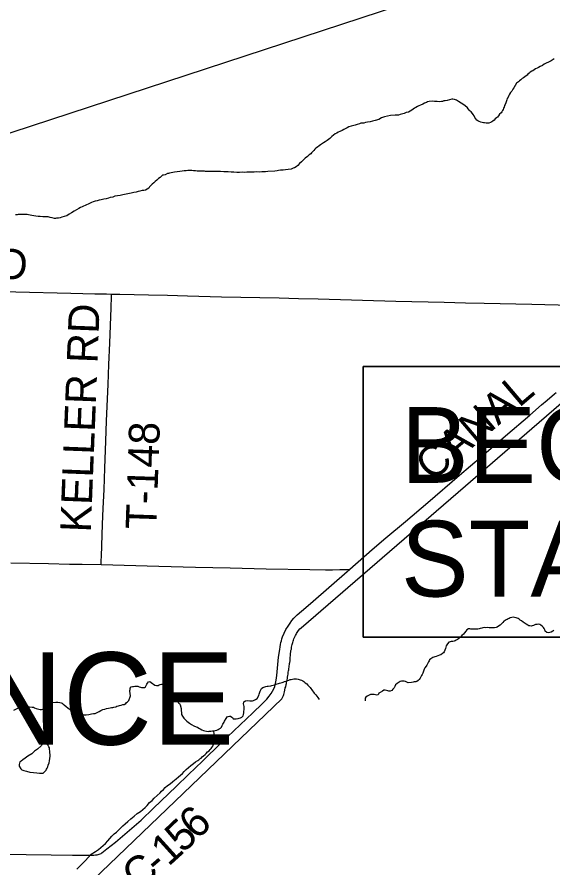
# Model space of a CAD drawing. Extents: x 0 to 34, y 0 to 22.
# Drawn here: x 24.635 to 25.625, y 15.894 to 17.466 of the extents above; entities that cross this region are included whole.
import ezdxf

# ---------------------------------------------------------------- set-up
doc = ezdxf.new("R2010")
doc.units = 0
for name, color, linetype in [('GM_X_County_Road', 7, 'Continuous'), ('GM_X_County_Road_Text', 7, 'Continuous'), ('GM_X_Minor_Lake', 7, 'Continuous'), ('GM_X_Minor_River', 7, 'Continuous'), ('GM_X_Rail_Line', 7, 'Continuous'), ('GM_X_Township_Road', 7, 'Continuous'), ('GM_X_Township_Road_Text', 7, 'Continuous'), ('GM_X_Township_Text', 7, 'Continuous'), ('SH_Masking', 7, 'Continuous'), ('SH_Text', 7, 'Continuous')]:
    doc.layers.add(name, color=color, linetype=linetype)

msp = doc.modelspace()

# ---------------------------------------------------------------- linework, layer by layer
at = {"layer": 'GM_X_County_Road'}
for points in [[(25.2499, 16.446), (25.2909, 16.4827), (25.3163, 16.5037), (25.3525, 16.5341), (25.3935, 16.5693), (25.4522, 16.6194), (25.4927, 16.6543), (25.5372, 16.6923), (25.582, 16.7308), (25.6039, 16.7493), (25.614, 16.7581), (25.6278, 16.7698), (25.6309, 16.7725)], [(24.6233, 16.4577), (24.6929, 16.4566), (24.7314, 16.4555), (24.755, 16.4552), (24.79, 16.4546)], [(24.79, 16.4546), (24.8967, 16.4517), (24.9645, 16.4499), (25.0285, 16.4483), (25.095, 16.4466), (25.1756, 16.4452), (25.2047, 16.445), (25.2176, 16.445), (25.2311, 16.4452), (25.2384, 16.4455), (25.2442, 16.4457), (25.2499, 16.446)], [(24.7913, 15.922), (24.8009, 15.9294), (24.8166, 15.9416), (24.8639, 15.9828), (24.8869, 16.0046), (24.9286, 16.0446), (24.9518, 16.0671), (24.9774, 16.0916), (25.0122, 16.1253), (25.0703, 16.1807), (25.0877, 16.1975), (25.096, 16.2058), (25.1008, 16.2114), (25.1046, 16.2165), (25.107, 16.2205), (25.1092, 16.2249), (25.1109, 16.2294), (25.1125, 16.2349), (25.1136, 16.241), (25.1145, 16.2494), (25.1179, 16.2834), (25.12, 16.2976), (25.1207, 16.3027), (25.1215, 16.3069), (25.1224, 16.3106), (25.1232, 16.3137), (25.1243, 16.3174), (25.1255, 16.3209), (25.1283, 16.3277), (25.1316, 16.3344), (25.1354, 16.3409), (25.1393, 16.3466), (25.1427, 16.3511), (25.1464, 16.3554), (25.1526, 16.3615), (25.1605, 16.3686), (25.1772, 16.3826), (25.2499, 16.446)]]:
    msp.add_lwpolyline(points, dxfattribs=at)
at = {"layer": 'GM_X_Minor_Lake'}
for points in [[(24.6836, 16.128), (24.6832, 16.1265), (24.6792, 16.1198), (24.6725, 16.1139), (24.667, 16.1099), (24.6619, 16.1048), (24.6549, 16.1008), (24.6499, 16.0972), (24.6456, 16.0939), (24.6421, 16.0917), (24.6401, 16.0903), (24.6384, 16.0854), (24.6387, 16.0823), (24.642, 16.0773), (24.6439, 16.0757), (24.6472, 16.0745), (24.6521, 16.0728), (24.6586, 16.0714), (24.6654, 16.0704), (24.6715, 16.0698), (24.6764, 16.0693)], [(24.6836, 16.128), (24.6832, 16.1265), (24.6792, 16.1198), (24.6725, 16.1139), (24.667, 16.1099), (24.6619, 16.1048), (24.6549, 16.1008), (24.6499, 16.0972), (24.6456, 16.0939), (24.6421, 16.0917), (24.6401, 16.0903), (24.6384, 16.0854), (24.6387, 16.0823), (24.642, 16.0773), (24.6439, 16.0757), (24.6472, 16.0745), (24.6521, 16.0728), (24.6586, 16.0714), (24.6654, 16.0704), (24.6715, 16.0698), (24.6764, 16.0693), (24.6806, 16.0695), (24.6829, 16.0695), (24.686, 16.0724), (24.6884, 16.0746), (24.6892, 16.0765), (24.6904, 16.0787), (24.6916, 16.081), (24.6925, 16.084), (24.6941, 16.0881), (24.695, 16.0919), (24.6955, 16.0961), (24.6957, 16.1006), (24.6958, 16.104), (24.6955, 16.1067), (24.6956, 16.1086), (24.6952, 16.1105), (24.6949, 16.1132), (24.6947, 16.1163), (24.6936, 16.1182), (24.6921, 16.1205), (24.6836, 16.128)], [(24.6764, 16.0693), (24.6806, 16.0695), (24.6829, 16.0695), (24.686, 16.0724), (24.6884, 16.0746), (24.6892, 16.0765), (24.6904, 16.0787), (24.6916, 16.081), (24.6925, 16.084), (24.6941, 16.0881), (24.695, 16.0919), (24.6955, 16.0961), (24.6957, 16.1006), (24.6958, 16.104), (24.6955, 16.1067), (24.6956, 16.1086), (24.6952, 16.1105), (24.6949, 16.1132), (24.6947, 16.1163), (24.6936, 16.1182), (24.6921, 16.1205), (24.6836, 16.128)]]:
    msp.add_lwpolyline(points, dxfattribs=at)
at = {"layer": 'GM_X_Minor_River'}
msp.add_line((23.5167, 14.667), (25.1242, 16.2064), dxfattribs=at)
for points in [[(25.1597, 16.3375), (27.0458, 17.9671)], [(25.6273, 17.3884), (25.6219, 17.3852), (25.6169, 17.3823), (25.6127, 17.3805), (25.6089, 17.3787), (25.6058, 17.3765), (25.6016, 17.3747), (25.5985, 17.3728), (25.5958, 17.3714), (25.5927, 17.37), (25.5904, 17.3681), (25.5877, 17.3667), (25.5858, 17.3656), (25.5831, 17.3641), (25.5807, 17.3619), (25.5788, 17.3604), (25.5772, 17.3586), (25.5753, 17.3571), (25.573, 17.3553), (25.5706, 17.3534), (25.5683, 17.352), (25.5656, 17.3497), (25.5633, 17.3479), (25.561, 17.3464), (25.5594, 17.3446), (25.5575, 17.3435), (25.5527, 17.3349), (25.5507, 17.3323), (25.5487, 17.3289), (25.5468, 17.3263), (25.5448, 17.3233), (25.5436, 17.3211), (25.542, 17.3181), (25.5404, 17.3151), (25.54, 17.3132), (25.5392, 17.3109), (25.5384, 17.309), (25.5376, 17.3072)], [(25.5376, 17.3072), (25.5364, 17.3045), (25.5355, 17.3023), (25.5347, 17.2993), (25.5335, 17.2974), (25.5327, 17.2951), (25.5319, 17.2929), (25.5307, 17.291), (25.5291, 17.2891), (25.5264, 17.2862), (25.5241, 17.2832), (25.5225, 17.281), (25.5205, 17.2795), (25.5182, 17.2776), (25.5163, 17.2754), (25.5139, 17.2736), (25.512, 17.2725), (25.5093, 17.271), (25.5066, 17.27), (25.504, 17.2696), (25.5013, 17.2697), (25.4983, 17.2702), (25.4964, 17.2702), (25.4941, 17.271), (25.4919, 17.2719), (25.4889, 17.2731), (25.4862, 17.2743), (25.4843, 17.2751), (25.4807, 17.2801), (25.4792, 17.2832), (25.4778, 17.2855), (25.4763, 17.2874), (25.4741, 17.2905), (25.4722, 17.2921), (25.4704, 17.2937), (25.4671, 17.2979), (25.4619, 17.3026), (25.4555, 17.3066), (25.4506, 17.3097), (25.4465, 17.3121), (25.4428, 17.3137), (25.4401, 17.3142), (25.4378, 17.3142), (25.434, 17.3132), (25.4294, 17.3118), (25.4256, 17.3111), (25.4233, 17.3108), (25.421, 17.3101), (25.4191, 17.3098), (25.4157, 17.3095), (25.4111, 17.3096), (25.4062, 17.3101), (25.4024, 17.3102), (25.396, 17.31), (25.3933, 17.3093), (25.391, 17.3082), (25.3879, 17.3068), (25.3844, 17.305), (25.3802, 17.3032), (25.3771, 17.3017), (25.3748, 17.3006), (25.3714, 17.2985), (25.3694, 17.2974), (25.3667, 17.2955), (25.364, 17.2941), (25.3613, 17.2922), (25.3579, 17.2904), (25.354, 17.2894), (25.3502, 17.2876), (25.3429, 17.2855), (25.3395, 17.2848), (25.3334, 17.2846), (25.325, 17.2837), (25.3193, 17.2827), (25.3136, 17.2813), (25.3082, 17.2795), (25.3032, 17.2766), (25.2963, 17.2749), (25.2917, 17.2735), (25.2871, 17.2721), (25.2822, 17.2715), (25.2784, 17.2708), (25.2753, 17.2701), (25.2723, 17.2698), (25.27, 17.2695), (25.2673, 17.2684), (25.2635, 17.2674), (25.2593, 17.2663), (25.2524, 17.2642), (25.2478, 17.2632), (25.2447, 17.2614), (25.2412, 17.2596), (25.2385, 17.2581), (25.2354, 17.2563), (25.2312, 17.2545), (25.2282, 17.2531), (25.2255, 17.2516), (25.2228, 17.2498), (25.2162, 17.245), (25.2127, 17.2417), (25.2103, 17.2395)], [(25.2103, 17.2395), (25.2076, 17.238), (25.2057, 17.2366), (25.2038, 17.2351), (25.2011, 17.2336), (25.1991, 17.2322), (25.1972, 17.2311), (25.1953, 17.2296), (25.193, 17.2281), (25.1899, 17.2256), (25.1871, 17.2234), (25.1852, 17.2215), (25.1832, 17.2193), (25.1809, 17.2171), (25.179, 17.2152), (25.1774, 17.2133), (25.1747, 17.2115), (25.1716, 17.2082), (25.1673, 17.2052), (25.1638, 17.2019), (25.1603, 17.1982), (25.1568, 17.1953), (25.1533, 17.1919), (25.1502, 17.1893), (25.1475, 17.1875), (25.1448, 17.1864), (25.141, 17.185), (25.136, 17.184), (25.1307, 17.1838), (25.1265, 17.1831), (25.1216, 17.1829), (25.1181, 17.1822), (25.1151, 17.1815), (25.1113, 17.1812), (25.0983, 17.1804), (25.0941, 17.1801), (25.0907, 17.1802), (25.0873, 17.1799), (25.0835, 17.1796), (25.0774, 17.1798), (25.0728, 17.1795), (25.0683, 17.1796), (25.0633, 17.179), (25.0592, 17.1791), (25.055, 17.1788), (25.0508, 17.179), (25.0459, 17.1787), (25.0409, 17.1788), (25.0356, 17.1793), (25.0303, 17.1795), (25.0246, 17.18), (25.0166, 17.1802), (25.0106, 17.1804), (25.0045, 17.1805), (24.9988, 17.1806), (24.9939, 17.1804), (24.9893, 17.1805), (24.9859, 17.1806), (24.9832, 17.1807), (24.981, 17.1811), (24.9791, 17.1811), (24.9772, 17.1812), (24.9737, 17.1813), (24.9707, 17.1814), (24.9677, 17.1814), (24.9643, 17.1819), (24.9609, 17.182), (24.9578, 17.1821), (24.9544, 17.1822), (24.9506, 17.1823), (24.9472, 17.182), (24.9434, 17.1817), (24.9396, 17.1814), (24.9357, 17.1803), (24.9304, 17.1797), (24.9258, 17.1791), (24.9224, 17.1788), (24.9194, 17.1781), (24.9167, 17.1774), (24.9148, 17.1771), (24.9129, 17.1771), (24.9082, 17.1746), (24.9052, 17.1739), (24.9033, 17.1736), (24.8994, 17.1695), (24.8963, 17.1673), (24.8928, 17.1647), (24.8901, 17.1621), (24.8874, 17.1595), (24.8846, 17.157), (24.8823, 17.1555), (24.8796, 17.1525), (24.878, 17.1499), (24.8753, 17.1481), (24.8718, 17.1463), (24.8688, 17.1456), (24.8661, 17.1453), (24.8619, 17.1442), (24.8585, 17.1436), (24.8546, 17.1425), (24.8504, 17.1415)], [(24.8504, 17.1415), (24.8459, 17.1405), (24.8302, 17.1374), (24.8252, 17.1364), (24.8203, 17.1354), (24.8157, 17.1348), (24.8115, 17.1334), (24.8069, 17.1323), (24.8035, 17.1313), (24.7993, 17.1303), (24.7951, 17.1292), (24.7901, 17.1282), (24.7863, 17.1275), (24.7828, 17.1265), (24.779, 17.1255), (24.7756, 17.1244), (24.7725, 17.1233), (24.7698, 17.1219), (24.7663, 17.1205), (24.7633, 17.119), (24.7606, 17.1179), (24.7575, 17.1165), (24.7548, 17.1154), (24.7521, 17.114), (24.7487, 17.1122), (24.7448, 17.1096), (24.7402, 17.1071), (24.7355, 17.1041), (24.7309, 17.1016), (24.7267, 17.0987), (24.7217, 17.0973), (24.7175, 17.0959), (24.7144, 17.0948), (24.7114, 17.0945), (24.7095, 17.0946), (24.7076, 17.0942), (24.7057, 17.0939), (24.7038, 17.0939), (24.6996, 17.0948), (24.6958, 17.0957), (24.6921, 17.0965), (24.6886, 17.097), (24.6856, 17.0971), (24.6826, 17.0971), (24.6776, 17.0973), (24.6739, 17.0977), (24.6693, 17.0982), (24.6655, 17.0987), (24.6621, 17.0992), (24.6587, 17.1), (24.6557, 17.1005), (24.6534, 17.1009), (24.6508, 17.101), (24.647, 17.1011), (24.6435, 17.1012), (24.6405, 17.1012), (24.6371, 17.101), (24.6348, 17.1006), (24.6321, 17.1003)], [(25.6191, 16.3289), (25.6168, 16.3286), (25.6138, 16.3291), (25.6108, 16.3318), (25.6097, 16.3341), (25.6086, 16.3364), (25.6072, 16.3384), (25.605, 16.3411), (25.6027, 16.3427), (25.6008, 16.3438), (25.599, 16.3443), (25.5959, 16.344), (25.5929, 16.3437), (25.589, 16.3422), (25.5867, 16.3412), (25.5848, 16.3408), (25.5822, 16.3413), (25.5803, 16.3417), (25.5784, 16.3425), (25.5754, 16.3445), (25.5735, 16.3457), (25.5717, 16.3472), (25.5698, 16.3484), (25.5668, 16.3508), (25.5646, 16.352), (25.5624, 16.3539), (25.5605, 16.3547), (25.5571, 16.356), (25.5541, 16.3568), (25.5514, 16.3573), (25.5488, 16.3569), (25.5461, 16.3559), (25.5442, 16.3552), (25.5422, 16.3544), (25.5403, 16.3534), (25.5384, 16.3526), (25.5365, 16.3515), (25.5341, 16.3501), (25.5322, 16.3475), (25.5302, 16.3456), (25.5275, 16.3427), (25.5244, 16.3405), (25.5221, 16.339), (25.5202, 16.3383), (25.5171, 16.3376), (25.5152, 16.3377), (25.5118, 16.3377), (25.5095, 16.3378), (25.5073, 16.3379), (25.5042, 16.3383), (25.5008, 16.338), (25.4978, 16.3381), (25.4955, 16.3378), (25.4936, 16.3371), (25.4905, 16.3364), (25.4886, 16.3357), (25.4863, 16.3353), (25.484, 16.3354), (25.4821, 16.3355), (25.4791, 16.3355), (25.4734, 16.3353), (25.4711, 16.3357), (25.4692, 16.3358), (25.4661, 16.334), (25.4638, 16.3314), (25.4618, 16.3284), (25.4595, 16.3258), (25.4568, 16.3236), (25.454, 16.3202), (25.4521, 16.3191), (25.4505, 16.3173), (25.4486, 16.3162), (25.4463, 16.3147), (25.4444, 16.314), (25.4424, 16.3133), (25.4401, 16.3126), (25.4371, 16.3123), (25.4352, 16.312), (25.4325, 16.3113), (25.4302, 16.3083), (25.429, 16.3064), (25.4278, 16.3042), (25.4261, 16.2993), (25.4249, 16.2966), (25.4237, 16.2936), (25.4225, 16.2918), (25.4206, 16.2903), (25.4179, 16.2881), (25.4152, 16.287), (25.4121, 16.286), (25.4091, 16.2849), (25.4064, 16.2842), (25.4029, 16.2828), (25.401, 16.2817), (25.3991, 16.2806), (25.3971, 16.2787), (25.3963, 16.2769), (25.3951, 16.275), (25.3936, 16.2724), (25.392, 16.269), (25.3908, 16.2671)], [(25.1242, 16.2064), (25.1261, 16.2104), (25.1269, 16.2127), (25.1277, 16.2145), (25.1286, 16.2172), (25.129, 16.2198), (25.1295, 16.2228), (25.1303, 16.2266), (25.1315, 16.2289), (25.132, 16.233), (25.1324, 16.2349), (25.1329, 16.2372), (25.1333, 16.2391), (25.1337, 16.2417), (25.1342, 16.2444), (25.1346, 16.2466), (25.1351, 16.2497), (25.1355, 16.2519), (25.1356, 16.2538), (25.136, 16.2557), (25.1364, 16.258), (25.1368, 16.2599), (25.1369, 16.2625), (25.1373, 16.2648), (25.1378, 16.2678), (25.1382, 16.2697), (25.1383, 16.2716), (25.1387, 16.2739), (25.1392, 16.2769), (25.1392, 16.2792), (25.1393, 16.2811), (25.1397, 16.2834), (25.1398, 16.286), (25.1398, 16.2883), (25.1403, 16.2902), (25.1407, 16.2932), (25.1408, 16.2959), (25.1416, 16.2985), (25.1421, 16.3019), (25.1425, 16.3042), (25.1433, 16.3072), (25.1442, 16.3106), (25.145, 16.3132), (25.1454, 16.3151), (25.1463, 16.3174), (25.1479, 16.3211), (25.1491, 16.3234), (25.1503, 16.3252), (25.1511, 16.3275), (25.1534, 16.3309), (25.155, 16.3327), (25.1574, 16.3361), (25.1597, 16.3375)], [(25.6264, 16.3326), (25.6245, 16.3315), (25.6218, 16.33), (25.6191, 16.3289)], [(25.3908, 16.2671), (25.388, 16.2638), (25.3872, 16.2615), (25.386, 16.2577), (25.3847, 16.254), (25.3832, 16.2517), (25.382, 16.2495), (25.3808, 16.2472), (25.3796, 16.245), (25.378, 16.2424), (25.3757, 16.2402), (25.3733, 16.2387), (25.3714, 16.238), (25.3688, 16.2377), (25.3665, 16.2374), (25.3638, 16.237), (25.3577, 16.2364), (25.3547, 16.2373), (25.3524, 16.2385), (25.3502, 16.2393), (25.3475, 16.2394), (25.3453, 16.2394), (25.3426, 16.2387), (25.3406, 16.2372), (25.3372, 16.2347), (25.3341, 16.2325), (25.3325, 16.2295), (25.3313, 16.2268), (25.3293, 16.2242), (25.327, 16.222), (25.3239, 16.221), (25.322, 16.221), (25.3201, 16.2214), (25.3171, 16.2219), (25.3148, 16.2223), (25.3125, 16.2224), (25.3102, 16.2205), (25.3056, 16.2184), (25.3033, 16.2173), (25.3021, 16.2139), (25.2998, 16.2136), (25.2968, 16.214), (25.2945, 16.2149), (25.2926, 16.2149), (25.2903, 16.2146), (25.2877, 16.2147), (25.2853, 16.2136), (25.2819, 16.2118), (25.2792, 16.2099), (25.278, 16.2081), (25.2778, 16.2032)], [(24.8441, 16.2121), (24.8434, 16.2206), (24.8434, 16.2217), (24.8435, 16.224), (24.8439, 16.2263), (24.8458, 16.2285), (24.8481, 16.2292), (24.8501, 16.2295), (24.8527, 16.2299), (24.8554, 16.2302), (24.8577, 16.2297), (24.8603, 16.2289), (24.8629, 16.2281), (24.8648, 16.2277), (24.8679, 16.2276), (24.8705, 16.2275), (24.8724, 16.229), (24.8736, 16.2312), (24.8745, 16.2335), (24.8757, 16.2357), (24.8776, 16.238), (24.8803, 16.2383), (24.8825, 16.2367), (24.8848, 16.2351), (24.887, 16.2335), (24.8896, 16.2316), (24.8926, 16.2311), (24.8953, 16.2314), (24.8972, 16.2325), (24.8995, 16.2329), (24.9018, 16.2336), (24.9041, 16.2339), (24.9064, 16.2346), (24.9083, 16.2345), (24.9109, 16.2329), (24.9116, 16.2306), (24.9116, 16.2284), (24.9108, 16.2265), (24.9099, 16.2223), (24.9095, 16.2204), (24.9098, 16.2178), (24.9116, 16.2158), (24.9139, 16.215), (24.9165, 16.2138), (24.9184, 16.2126), (24.9206, 16.2118), (24.9267, 16.2107)], [(25.0786, 16.2074), (25.0817, 16.2127), (25.0822, 16.2153), (25.0834, 16.2187), (25.0842, 16.2206), (25.085, 16.2232), (25.0862, 16.2255), (25.0889, 16.2277), (25.0924, 16.2287), (25.0947, 16.2294), (25.097, 16.2297), (25.0989, 16.2301), (25.1034, 16.2307), (25.1054, 16.2314), (25.1077, 16.2321), (25.1103, 16.2324), (25.1122, 16.2332), (25.1153, 16.2342), (25.1176, 16.2349), (25.1195, 16.2353), (25.1222, 16.2359), (25.1245, 16.2366), (25.1264, 16.2374), (25.1287, 16.2384), (25.1322, 16.2395), (25.1345, 16.2406), (25.1368, 16.2413), (25.1391, 16.242), (25.141, 16.2423), (25.144, 16.243), (25.1463, 16.2433), (25.149, 16.2436), (25.1512, 16.2436), (25.1543, 16.2427), (25.1577, 16.2419), (25.1603, 16.2411), (25.1626, 16.2399), (25.1644, 16.2383), (25.167, 16.2359), (25.17, 16.234), (25.1719, 16.232), (25.1741, 16.2301), (25.1763, 16.2277), (25.1778, 16.2254), (25.1792, 16.2235), (25.184, 16.2169), (25.1866, 16.2138), (25.1884, 16.2115), (25.1906, 16.2088), (25.1928, 16.2051)], [(24.7065, 16.2003), (24.7103, 16.2002), (24.7137, 16.1997), (24.716, 16.1993), (24.7182, 16.1984), (24.7201, 16.1968), (24.7219, 16.1956), (24.7257, 16.1925), (24.7286, 16.1897), (24.7308, 16.1881), (24.7342, 16.1853), (24.736, 16.1838), (24.7383, 16.1822), (24.742, 16.1805), (24.7462, 16.1792), (24.7503, 16.178), (24.7541, 16.1771), (24.7625, 16.1768), (24.7675, 16.1778), (24.7721, 16.1788), (24.7759, 16.1794), (24.7793, 16.1797), (24.7816, 16.1807), (24.784, 16.1818), (24.7867, 16.1832), (24.7898, 16.185), (24.7933, 16.1868), (24.7967, 16.1878), (24.7998, 16.1889), (24.804, 16.1895), (24.8067, 16.1898), (24.8094, 16.1905), (24.8117, 16.1908), (24.8136, 16.1911), (24.817, 16.1921), (24.819, 16.1928), (24.8221, 16.1938), (24.824, 16.1945), (24.827, 16.1952), (24.8301, 16.1959), (24.8324, 16.1962), (24.8355, 16.198), (24.8371, 16.1998), (24.839, 16.2013), (24.841, 16.2035), (24.8441, 16.2121)], [(24.9267, 16.2107), (24.9331, 16.1993), (24.9349, 16.1981), (24.936, 16.1954), (24.9377, 16.1889), (24.938, 16.187), (24.9383, 16.1843), (24.9386, 16.1812), (24.9388, 16.1778), (24.9403, 16.1743), (24.9432, 16.1708), (24.9458, 16.1681), (24.9487, 16.1653), (24.951, 16.1637), (24.9536, 16.1617), (24.9569, 16.1593), (24.9614, 16.1569), (24.9659, 16.1548), (24.9682, 16.1544), (24.9708, 16.1524), (24.9734, 16.1512), (24.976, 16.1496), (24.979, 16.1479), (24.9817, 16.1475), (24.9847, 16.1466), (24.9877, 16.1465), (24.9896, 16.1468), (24.9927, 16.1467), (24.9958, 16.1474), (24.9984, 16.1477), (25.0011, 16.148), (25.0038, 16.1486), (25.0061, 16.1497), (25.0084, 16.1512), (25.0108, 16.1526), (25.0124, 16.1545), (25.0136, 16.1575), (25.0152, 16.1597), (25.016, 16.1616), (25.0172, 16.1634), (25.018, 16.1653), (25.0209, 16.1705), (25.0229, 16.1731), (25.0248, 16.1742), (25.0271, 16.1745), (25.0294, 16.1744), (25.0316, 16.1728), (25.0335, 16.1716), (25.0338, 16.1697), (25.0376, 16.1696), (25.0399, 16.1699), (25.0433, 16.1705), (25.0453, 16.1709), (25.0476, 16.1712), (25.0503, 16.1726), (25.0523, 16.1752), (25.0531, 16.1775), (25.0536, 16.1805), (25.054, 16.1835), (25.0541, 16.1866), (25.0542, 16.1896), (25.0543, 16.1926), (25.054, 16.1949), (25.0533, 16.1976), (25.0538, 16.201), (25.0566, 16.2032), (25.0608, 16.2035), (25.0646, 16.2029), (25.0668, 16.2029), (25.0695, 16.2032), (25.0714, 16.2035), (25.0741, 16.2049), (25.0753, 16.2053), (25.0786, 16.2074)], [(24.6287, 16.1854), (24.6361, 16.1893), (24.6384, 16.1904), (24.6403, 16.1911), (24.6434, 16.1921), (24.6453, 16.1925), (24.6476, 16.192), (24.6529, 16.1918), (24.6578, 16.1917), (24.6624, 16.1915), (24.6651, 16.191), (24.6673, 16.1898), (24.6699, 16.189), (24.6726, 16.1881), (24.6748, 16.1873), (24.6775, 16.1868), (24.6798, 16.1871), (24.6825, 16.1874), (24.6855, 16.1885), (24.6875, 16.1892), (24.6898, 16.1906), (24.693, 16.1943), (24.6953, 16.1973), (24.6969, 16.1991), (24.7011, 16.2001), (24.7065, 16.2003)], [(24.745, 15.892), (24.7489, 15.8957), (24.7529, 15.8994), (24.7572, 15.9038), (24.7615, 15.9082), (24.7663, 15.9134), (24.7718, 15.92), (24.7796, 15.9244), (24.785, 15.9284), (24.7897, 15.932), (24.794, 15.9357), (24.7979, 15.9397), (24.8023, 15.9441), (24.8062, 15.9486), (24.8102, 15.953), (24.8145, 15.9571), (24.8184, 15.9604), (24.8219, 15.9637), (24.8267, 15.9681), (24.8302, 15.9718), (24.8345, 15.9758), (24.8392, 15.9802), (24.8447, 15.985), (24.851, 15.9901), (24.8568, 15.9948), (24.8627, 15.9985), (24.8673, 16.0021), (24.8717, 16.0058), (24.8752, 16.0095), (24.8792, 16.015), (24.8843, 16.0191), (24.8882, 16.0231), (24.8992, 16.033), (24.9019, 16.036), (24.9051, 16.0389), (24.9086, 16.0426), (24.9129, 16.0463), (24.9176, 16.0499), (24.9223, 16.0539), (24.9286, 16.0587), (24.9329, 16.0623), (24.9368, 16.0656), (24.9403, 16.0689), (24.9438, 16.0723), (24.9474, 16.0759), (24.9517, 16.08), (24.956, 16.0836), (24.9607, 16.0873), (24.9646, 16.0902), (24.9685, 16.0927), (24.9704, 16.0942), (24.9728, 16.0956), (24.9747, 16.0971), (24.9771, 16.0993), (24.9794, 16.1015), (24.9822, 16.1037), (24.9845, 16.1059), (24.9869, 16.1085), (24.9896, 16.1107), (24.9916, 16.1129), (24.9932, 16.1148), (24.9948, 16.1166), (24.9964, 16.1192), (24.998, 16.123), (24.9985, 16.1249), (24.9989, 16.1271), (24.9994, 16.1298), (24.9995, 16.1324), (25, 16.1358), (24.9997, 16.1385), (24.999, 16.1412), (24.9984, 16.1477)]]:
    msp.add_lwpolyline(points, dxfattribs=at)
at = {"layer": 'GM_X_Rail_Line'}
msp.add_lwpolyline([(23.7996, 16.983), (25.7008, 17.6061), (26.4117, 17.837), (26.5031, 17.869), (26.5924, 17.903), (26.691, 17.9509), (26.7753, 17.9922), (26.8457, 18.0296)], dxfattribs=at)
at = {"layer": 'GM_X_Township_Road'}
for points in [[(23.8004, 16.9788), (23.8095, 16.9786), (23.8319, 16.9779), (23.8872, 16.9765), (23.9469, 16.9748), (23.9699, 16.9745), (24.0102, 16.9736), (24.0556, 16.9726), (24.0811, 16.9717), (24.0985, 16.9714), (24.1215, 16.971), (24.1787, 16.9697), (24.3154, 16.9661), (24.4117, 16.9637), (24.4906, 16.9618), (24.513, 16.9613), (24.5366, 16.9607), (24.6323, 16.9582), (24.7342, 16.9558), (24.7783, 16.9547), (24.8, 16.9543), (24.8093, 16.9542)], [(24.79, 16.4546), (24.7903, 16.4616), (24.7907, 16.4698), (24.7921, 16.5089), (24.7929, 16.5294), (24.7941, 16.5579), (24.7955, 16.5933), (24.7968, 16.6325), (24.7988, 16.6827), (24.8003, 16.72), (24.803, 16.7871), (24.8046, 16.8243), (24.8061, 16.8634), (24.8085, 16.9286), (24.8092, 16.9497), (24.8093, 16.9542)], [(24.8093, 16.9542), (24.8137, 16.9541), (24.8249, 16.9541), (24.8777, 16.9528), (24.9125, 16.9519), (24.9498, 16.9508), (25.0126, 16.9493), (25.1189, 16.9469), (25.1549, 16.9461), (25.1909, 16.9452), (25.3345, 16.9412), (25.424, 16.939), (25.4631, 16.938), (25.4979, 16.9373), (25.5862, 16.9352), (25.6589, 16.9336), (25.6899, 16.9329), (25.7254, 16.9322), (25.8152, 16.9305)], [(24.5829, 15.92), (24.6519, 15.919), (24.6979, 15.9182), (24.737, 15.9177), (24.7612, 15.9177), (24.7718, 15.9178), (24.7769, 15.918), (24.78, 15.9183), (24.7825, 15.9185), (24.7846, 15.9189), (24.7864, 15.9195), (24.7882, 15.9202), (24.7899, 15.9211), (24.7913, 15.922)]]:
    msp.add_lwpolyline(points, dxfattribs=at)
at = {"layer": 'SH_Masking'}
msp.add_lwpolyline([(25.2742, 16.8205), (27.0187, 16.8205), (27.0187, 16.3205), (25.2742, 16.3205)], close=True, dxfattribs=at)
at = {"layer": 'SH_Text'}
msp.add_lwpolyline([(25.2742, 16.3205), (27.0187, 16.3205), (27.0187, 16.8205), (25.2742, 16.8205)], close=True, dxfattribs=at)

# ---------------------------------------------------------------- texts
at = {"layer": 'GM_X_County_Road_Text'}
for s, height, rotation, p in [('CANAL', 0.05682, 40.3875, (25.4015, 16.6065)), ('6', 0.0568, 43.8052, (24.967, 15.9445)), ('5', 0.0568, 43.4837, (24.9413, 15.9202)), ('1', 0.0568, 42.2546, (24.9144, 15.8957)), ('C', 0.0568, 39.3401, (24.8583, 15.8488)), ('-', 0.0568, 40.7334, (24.8955, 15.8794))]:
    msp.add_text(s, height=height, rotation=rotation, dxfattribs=at).set_placement(p)
at = {"layer": 'GM_X_Township_Road_Text'}
for s, rotation, p in [('RD', 358.5089, (24.5441, 16.9834)), ('KELLER RD', 87.739, (24.771, 16.5134)), ('T-148', 88.0353, (24.892, 16.5189))]:
    msp.add_text(s, height=0.05682, rotation=rotation, dxfattribs=at).set_placement(p)
at = {"layer": 'GM_X_Township_Text'}
msp.add_text('DEFIANCE', height=0.17045, rotation=0, dxfattribs=at).set_placement((23.8838, 16.1219))
at = {"layer": 'SH_Text'}
for s, p in [('BEGIN PROJECT', (25.3442, 16.6055)), ('STA. 224+10.00', (25.3442, 16.3955))]:
    msp.add_text(s, height=0.14, dxfattribs=at).set_placement(p)

doc.saveas('drawing.dxf')
